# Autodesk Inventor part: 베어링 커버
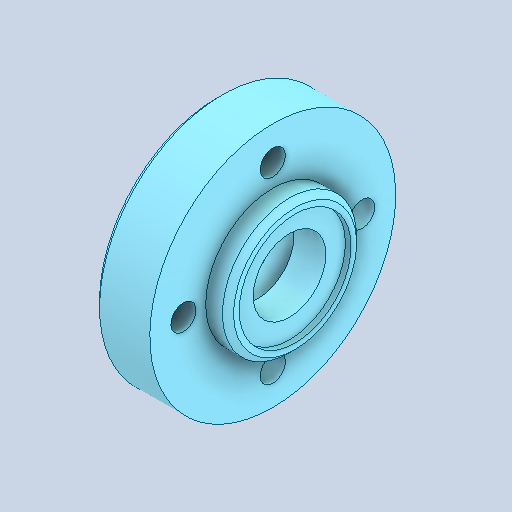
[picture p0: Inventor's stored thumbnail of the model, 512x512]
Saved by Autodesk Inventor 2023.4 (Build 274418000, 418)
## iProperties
Created: 2024-05
Part Number: 베어링 커버
Material: 강철, 연강
Document SubType Name: Modeling
Designer: edu-40
Density: 7.85 g/cm^3
Appearance: 기본값
Author: jhkim
Sending System: Autodesk Inventor 2025
Preprocessor: ST-DEVELOPER v20
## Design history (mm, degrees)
feature "솔리드1"
node "솔리드2"
